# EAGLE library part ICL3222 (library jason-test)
1uA supply current dual RS232 transmitter/receiver
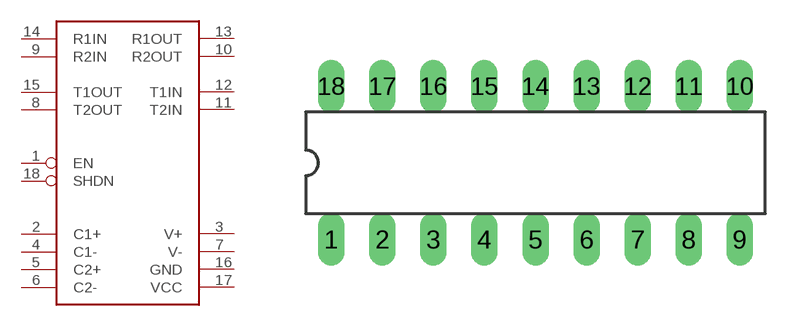
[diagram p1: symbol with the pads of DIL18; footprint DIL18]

Designator prefix -

## ICL3222  [DIL18]
1  EN  in
2  C1+  pas
3  V+  pwr
4  C1-  pas
5  C2+  pas
6  C2-  pas
7  V-  pwr
8  T2OUT  out
9  R2IN  in
10  R2OUT  out
11  T2IN  in
12  T1IN  in
13  R1OUT  out
14  R1IN  in
15  T1OUT  out
16  GND  pwr
17  VCC  pwr
18  SHDN  in

## Footprint DIL18 (pad centres in mm)
Dual In Line package type P
drill 0.813 long: 1 -10.16,-3.81; 2 -7.62,-3.81; 3 -5.08,-3.81; 4 -2.54,-3.81; 5 0,-3.81; 6 2.54,-3.81; 7 5.08,-3.81; 8 7.62,-3.81; 9 10.16,-3.81; 10 10.16,3.81; 11 7.62,3.81; 12 5.08,3.81; 13 2.54,3.81; 14 0,3.81; 15 -2.54,3.81; 16 -5.08,3.81; 17 -7.62,3.81; 18 -10.16,3.81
